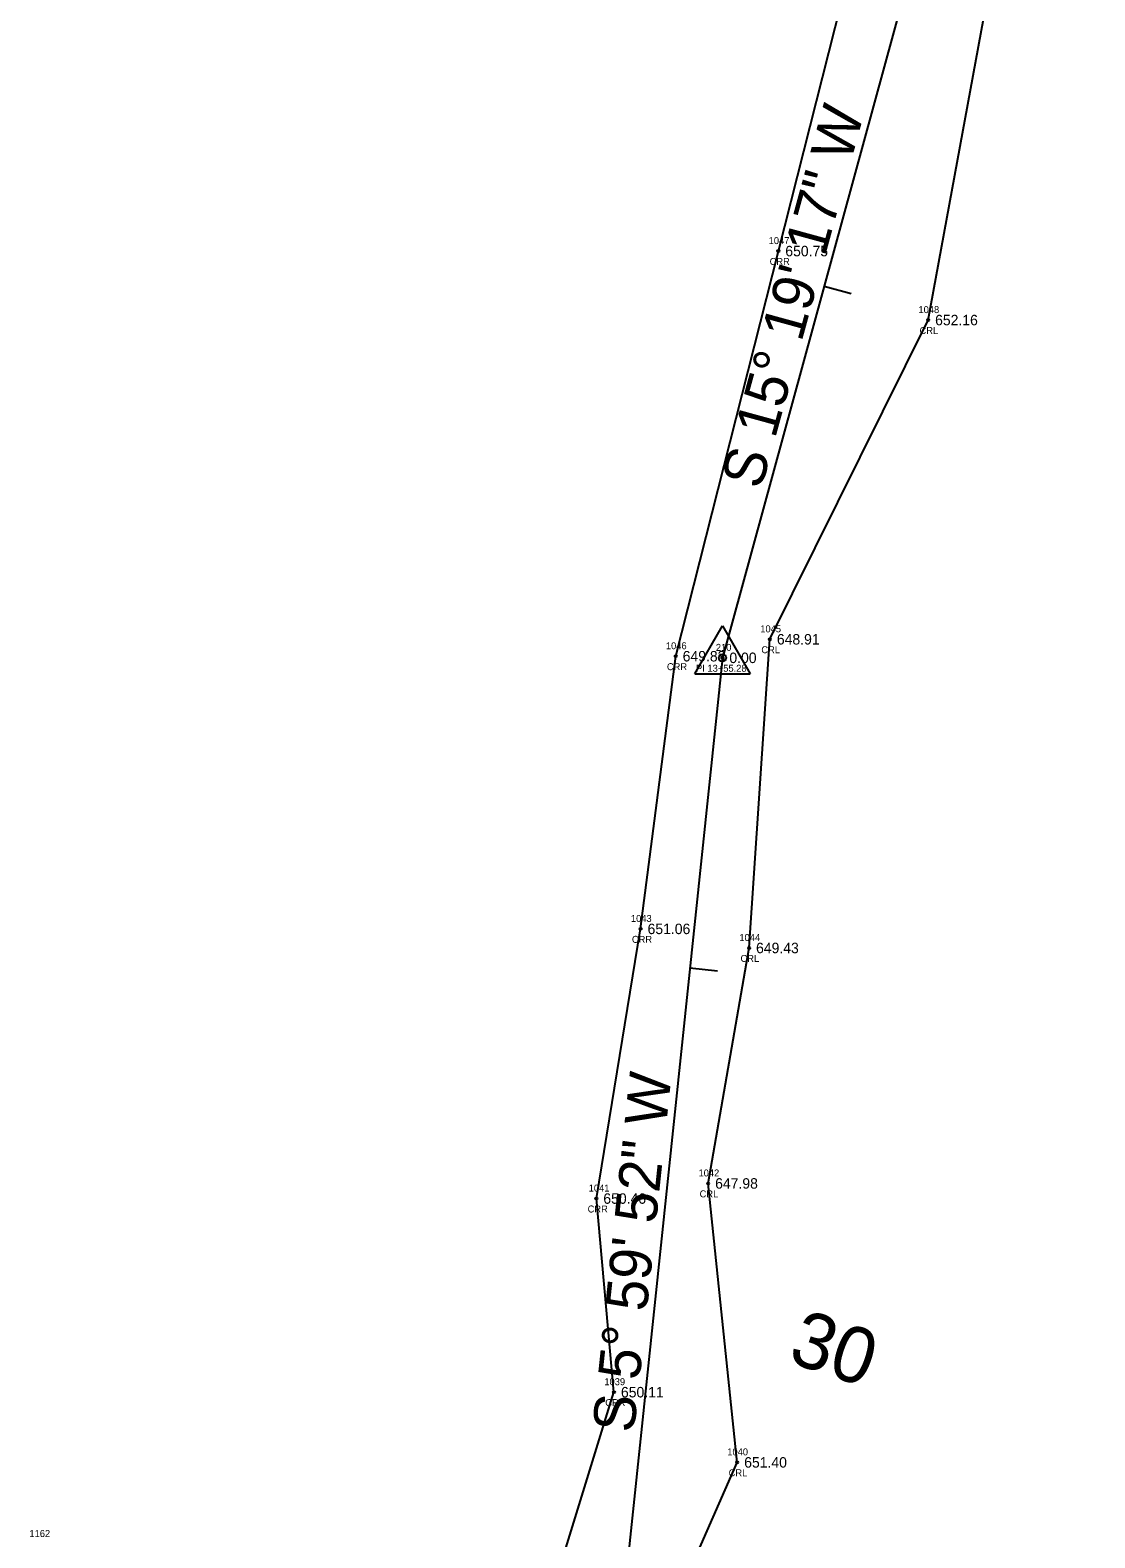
# Model space of a CAD drawing. Extents: x 1655137 to 1657928, y 1003994 to 1005407.
# Drawn here: x 1656289.3 to 1656442.1, y 1004705.8 to 1004922.1 of the extents above; entities that cross this region are included whole.
import ezdxf

# ---------------------------------------------------------------- set-up
doc = ezdxf.new("R2010")
doc.units = 0
for name, color, linetype in [('RD_EX_H2O', 7, 'Continuous'), ('RD_EX_H2O_txCode', 7, 'Continuous'), ('RD_EX_TX_H2O_ELEV', 7, 'Continuous'), ('RD_EX_VEG_txCode', 7, 'Continuous'), ('RD_HC_Cl', 7, 'Continuous'), ('RD_HC_Data', 7, 'Continuous'), ('RD_HC_Data_Tic', 7, 'Continuous'), ('RD_HC_Survey_ELEV', 7, 'Continuous'), ('RD_HC_TX_Sta50', 7, 'Continuous'), ('RD_HC_txCode', 7, 'Continuous'), ('RD_SMD_Locator', 7, 'Continuous')]:
    doc.layers.add(name, color=color, linetype=linetype)

msp = doc.modelspace()

# ---------------------------------------------------------------- linework, layer by layer
at = {"layer": 'RD_EX_H2O'}
for points in [[(1656396.09, 1004633.07), (1656383.79, 1004647.24), (1656376.78, 1004660.97), (1656381.31, 1004695.03), (1656390.77, 1004716.64), (1656386.6, 1004756.66), (1656392.47, 1004790.44), (1656395.46, 1004834.73), (1656418.17, 1004880.53), (1656428.48, 1004936.46), (1656416.99, 1004968.14), (1656420.24, 1005011.82), (1656412.2, 1005039.74), (1656428.37, 1005086.9), (1656442.1, 1005137.22), (1656437.49, 1005175.75)], [(1656368.16, 1004641.29), (1656363.88, 1004666), (1656364.85, 1004699.99), (1656373.08, 1004726.71), (1656370.55, 1004754.49), (1656376.9, 1004793.18), (1656381.94, 1004832.3), (1656396.67, 1004890.43), (1656408.46, 1004936.92), (1656401.87, 1004961.79), (1656402.89, 1005007.98), (1656396.57, 1005037.78), (1656403.09, 1005084.85)]]:
    msp.add_lwpolyline(points, dxfattribs=at)
at = {"layer": 'RD_HC_Cl'}
for p, q in [((1656416.76, 1004934.7), (1656388.64, 1004832.07)), ((1656388.64, 1004832.07), (1656370.75, 1004661.76))]:
    msp.add_line(p, q, dxfattribs=at)
at = {"layer": 'RD_HC_Data'}
for p, q in [((1656384.67, 1004829.78), (1656388.64, 1004836.66)), ((1656388.64, 1004836.66), (1656392.61, 1004829.78)), ((1656384.67, 1004829.78), (1656392.61, 1004829.78))]:
    msp.add_line(p, q, dxfattribs=at)
msp.add_circle((1656388.64, 1004832.07), 0.529, dxfattribs=at)
at = {"layer": 'RD_HC_Data_Tic'}
for p, q in [((1656403.25, 1004885.38), (1656407.11, 1004884.33)), ((1656383.97, 1004787.59), (1656387.95, 1004787.18))]:
    msp.add_line(p, q, dxfattribs=at)
at = {"layer": 'RD_SMD_Locator'}
for centre in [(1656396.67, 1004890.43), (1656418.17, 1004880.53), (1656395.46, 1004834.73), (1656381.94, 1004832.3), (1656388.64, 1004832.07), (1656376.9, 1004793.18), (1656392.47, 1004790.44), (1656386.6, 1004756.66), (1656370.55, 1004754.49), (1656373.08, 1004726.71), (1656390.77, 1004716.64)]:
    msp.add_circle(centre, 0.15, dxfattribs=at)

# ---------------------------------------------------------------- texts
at = {"layer": 'RD_EX_H2O_txCode'}
for s, p in [('1047', (1656395.28, 1004891.43)), ('CRR', (1656395.42, 1004888.43)), ('1048', (1656416.78, 1004881.53)), ('CRL', (1656416.94, 1004878.53)), ('1045', (1656394.08, 1004835.73)), ('1046', (1656380.53, 1004833.3)), ('CRL', (1656394.23, 1004832.73)), ('CRR', (1656380.68, 1004830.3)), ('1043', (1656375.51, 1004794.18)), ('CRR', (1656375.65, 1004791.18)), ('1044', (1656391.08, 1004791.44)), ('CRL', (1656391.24, 1004788.44)), ('1042', (1656385.21, 1004757.66)), ('1041', (1656369.45, 1004755.49)), ('CRL', (1656385.37, 1004754.66)), ('CRR', (1656369.3, 1004752.49)), ('1039', (1656371.7, 1004727.71)), ('CRR', (1656371.83, 1004724.71)), ('1040', (1656389.34, 1004717.64)), ('CRL', (1656389.54, 1004714.64))]:
    msp.add_text(s, height=1, dxfattribs=at).set_placement(p)
at = {"layer": 'RD_EX_TX_H2O_ELEV'}
for s, p in [('650.75', (1656397.67, 1004889.68)), ('652.16', (1656419.17, 1004879.78)), ('648.91', (1656396.46, 1004833.98)), ('649.83', (1656382.94, 1004831.55)), ('651.06', (1656377.9, 1004792.43)), ('649.43', (1656393.47, 1004789.69)), ('647.98', (1656387.6, 1004755.91)), ('650.46', (1656371.55, 1004753.74)), ('650.11', (1656374.08, 1004725.96)), ('651.40', (1656391.77, 1004715.89))]:
    msp.add_text(s, height=1.5, dxfattribs=at).set_placement(p)
at = {"layer": 'RD_EX_VEG_txCode'}
msp.add_text('1162', height=1, dxfattribs=at).set_placement((1656289.18, 1004705.93))
at = {"layer": 'RD_HC_Data'}
for s, rotation, p in [('S 15%%d 19\' 17" W', 74.6785, (1656394.18, 1004856.08)), ('S 5%%d 59\' 52" W', 84.0023, (1656375.94, 1004720.78))]:
    msp.add_text(s, height=6, rotation=rotation, dxfattribs=at).set_placement(p)
at = {"layer": 'RD_HC_Survey_ELEV'}
msp.add_text('0.00', height=1.5, dxfattribs=at).set_placement((1656389.64, 1004831.32))
at = {"layer": 'RD_HC_TX_Sta50'}
msp.add_text('30', height=8, rotation=341.5604, dxfattribs=at).set_placement((1656397.83, 1004731.13))
at = {"layer": 'RD_HC_txCode'}
for s, p in [('210', (1656387.7, 1004833.07)), ('PI 13+55.28', (1656384.86, 1004830.07))]:
    msp.add_text(s, height=1, dxfattribs=at).set_placement(p)

doc.saveas('drawing.dxf')
